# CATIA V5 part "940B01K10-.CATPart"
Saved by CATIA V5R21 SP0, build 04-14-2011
Part number: 940B01K10-
Bounding box of the stored display mesh (mm): x -77.949 to 49.351, y -15.698 to 19.302, z -6.85 to 7.15
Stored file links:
  C:\Users\ALI OZGUN\Desktop\alhan\940B01K10-.CATPart
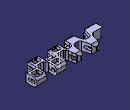
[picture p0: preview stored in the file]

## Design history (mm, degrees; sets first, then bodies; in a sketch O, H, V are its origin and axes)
Set1 "CURVE"
  DatumCurve1 to DatumCurve105
Set2 "SURFACE"
  Plane1: type 1Curve, Element1 DatumCurve19
  Sketch1 on Plane1, origin (0, 0, -3.1959), H (1, 0, 0), V (0, -1, 0)
    line L1 (49.4472, 15.9983) -> (32.7694, 15.9983)
    line L2 (48.5473, -19.0017) -> (65.7661, -19.0017)
    line L3 (-61.2339, -0.5841) -> (-61.2339, 15.0809)
    line L4 (65.7661, -19.0017) -> (65.7661, 3.0782)
    point P1 (65.7661, -19.0017)
    line L5 (49.4472, 15.9983) -> (49.0081, 3.1001)
    line L6 (49.0081, 3.1001) -> (53.2715, -2.5577)
    line L7 (53.2715, -2.5577) -> (61.843, -2.5577)
    point P2 (49.0081, 3.1001)
    point P3 (53.2715, -2.5577)
    point P4 (49.4472, 15.9983)
    line L8 (61.843, -2.5577) -> (65.7661, 3.0782)
    point P5 (61.843, -2.5577)
    point P6 (65.7661, 3.0782)
    reference intersected line E1 through (0, 0) direction (0, 1) from yz-plane
    reference intersected line E2 through (0, 0) direction (0, 1) from yz-plane
    construction line L9 (41.1083, 0) -> (41.1083, 12.9106)
    construction line L10 (41.1083, 12.9106) -> (46.3559, 12.9106)
    construction line L11 (46.3559, 12.9106) -> (46.3559, 3.0133)
    construction line L12 (46.3559, 3.0133) -> (41.1083, 3.0133)
    point P7 (46.3559, 12.9106)
    point P8 (46.3559, 3.0133)
    point P9 (41.1083, 12.9106)
    point P10 (41.1083, 3.0133)
    line L13 (41.1083, 0) -> (50.5276, 0)
    line L14 (48.5473, -19.0017) -> (50.5276, 0)
    point P11 (50.5276, 0)
    point P12 (41.1083, 0)
    point P13 (48.5473, -19.0017)
    point P14 (35.8607, 12.9106)
    point P15 (41.1083, 12.9106)
    construction line L15 (41.1083, 12.9106) -> (35.8607, 12.9106)
    point P16 (35.8607, 3.0133)
    construction line L16 (35.8607, 12.9106) -> (35.8607, 3.0133)
    point P17 (41.1083, 3.0133)
    construction line L17 (35.8607, 3.0133) -> (41.1083, 3.0133)
    point P18 (31.6891, 0)
    point P19 (41.1083, 0)
    line L18 (41.1083, 0) -> (31.6891, 0)
    point P20 (33.6694, -19.0017)
    line L19 (33.6694, -19.0017) -> (31.6891, 0)
    point P21 (16.4506, -19.0017)
    line L20 (33.6694, -19.0017) -> (16.4506, -19.0017)
    point P22 (16.4506, 3.0782)
    line L21 (16.4506, -19.0017) -> (16.4506, 0)
    point P23 (20.3736, -2.5577)
    line L22 (20.3736, -2.5577) -> (16.5464, 2.9405)
    point P24 (28.9451, -2.5577)
    line L23 (28.9451, -2.5577) -> (20.3736, -2.5577)
    point P25 (33.2086, 3.1001)
    line L24 (33.2086, 3.1001) -> (28.9451, -2.5577)
    point P26 (32.7694, 15.9983)
    line L25 (32.7694, 15.9983) -> (33.2086, 3.1001)
    axis line L26 (24.8802, -15.8106) -> (24.8802, 20.8842)
    line L27 (16.991, 15.9983) -> (16.5464, 2.9405)
    point P29 (13.8998, 3.0133)
    point P30 (13.8998, 12.9106)
    construction line L28 (13.8998, 12.9106) -> (13.8998, 3.0133)
    point P31 (8.6521, 0)
    line L29 (8.6521, 0) -> (16.4506, 0)
    point P32 (8.6521, 0)
    line L30 (8.6521, 0) -> (-0.2618, 0)
    point P33 (3.4045, 3.0133)
    point P34 (3.4045, 12.9106)
    construction line L31 (3.4045, 12.9106) -> (3.4045, 3.0133)
    point P35 (8.6521, 3.0133)
    construction line L32 (3.4045, 3.0133) -> (8.6521, 3.0133)
    point P36 (8.6521, 3.0133)
    construction line L33 (13.8998, 3.0133) -> (8.6521, 3.0133)
    point P37 (8.6521, 12.9106)
    construction line L34 (8.6521, 12.9106) -> (3.4045, 12.9106)
    point P38 (8.6521, 12.9106)
    construction line L35 (8.6521, 12.9106) -> (13.8998, 12.9106)
    point P39 (0.3133, 15.9983)
    line L36 (0.3133, 15.9983) -> (0.7524, 3.1001)
    line L37 (0.7524, 3.1001) -> (-3.8134, -2.9589)
    line L38 (16.991, 15.9983) -> (0.3133, 15.9983)
    line L39 (-0.2618, 0) -> (0.5916, -19.0017)
    line L40 (-12.1477, -5.1469) -> (-12.4932, -19.0017)
    line L41 (-3.8134, -2.9589) -> (-12.4906, -2.9589)
    line L42 (-12.4906, -2.9589) -> (-12.6654, 12.1222)
    line L43 (-29.6656, -3.0126) -> (-25.0164, 15.9983)
    line L44 (-39.0662, -3.1542) -> (-29.6656, -3.0126)
    line L45 (-44.327, 15.3928) -> (-39.0662, -3.1542)
    line L46 (-43.9186, 0.391) -> (-38.7475, -19.0017)
    line L47 (-43.9186, 0.391) -> (-61.2339, -0.5841)
    line L48 (-61.2339, 15.0809) -> (-44.327, 15.3928)
    line L49 (-16.4275, 15.9983) -> (-25.0164, 15.9983)
    line L50 (-16.4275, 15.9983) -> (-12.6654, 12.1222)
    line L51 (-24.9197, 0.2086) -> (-29.3974, -19.0017)
    line L52 (-24.9197, 0.2086) -> (-16.3942, 0.2086)
    line L53 (-16.3942, 0.2086) -> (-12.1477, -5.1469)
    line L54 (-29.3974, -19.0017) -> (-38.7475, -19.0017)
    line L55 (0.5916, -19.0017) -> (-12.4932, -19.0017)
    distance L2 L1 = 35
    distance L3 L4 = 127
    angle E1 L5 = 1.95
    angle E2 L6 = 37
    horizontal: L1 H, L2 H, L7 H, L10 H, L12 H, L13 H, L38 H, L41 H, L49 H, L52 H
    fix: L1, L9
    vertical: L3 V, L4 V, L9 V, L11 V, L26 V
    coincidence: P10 L9, L1 L38, P22 L22, P22 L21, L38 L49, L20 L54, L20 L55
    symmetry: P7 P14 L9, P9 P15 L9, L10 L15 L9, P8 P16 L9, L11 L16 L9, P10 P17 L9, L12 L17 L9, P11 P18 L9, P12 P19 L9, L13 L18 L9, P13 P20 L9, L14 L19 L9, P1 P21 L9, L2 L20 L9, P6 P22 L9, L4 L21 L9, P5 P23 L9, L8 L22 L9, P3 P24 L9, L7 L23 L9, P2 P25 L9, L6 L24 L9, P4 P26 L9, L5 L25 L9, L25 L27 L26, P16 P29 L26, P14 P30 L26, L16 L28 L26, P19 P31 L26, L18 L29 L26, P12 P32 L26, L13 L30 L26, P8 P33 L26, P7 P34 L26, L11 L31 L26, P10 P35 L26, L12 L32 L26, P17 P36 L26, L17 L33 L26, P9 P37 L26, L10 L34 L26, P15 P38 L26, L15 L35 L26, P4 P39 L26, L5 L36 L26, L6 L37 L26
  Sweep1: type Segment, GuideCrv Sketch1, Length1 4, Length2 5, Angle -1, DraftDirection (0, 0, 1)
  Sketch2 on yz-plane, origin (0, 0, 0), H (0, 1, 0), V (0, 0, 1)
    line L1 (-24.9191, -6.9968) -> (50.389, -6.9968)
    horizontal: L1 H
  Extrude1: Element1 Sketch2, Lim1 80, Lim2 80
  Trim1: Trimmed (Sweep1; Extrude1)
  Sketch3 on yz-plane, origin (0, 0, 0), H (0, 1, 0), V (0, 0, 1)
    line L1 (-48.3055, 0) -> (52.6647, 0)
    horizontal: L1 H
    coincidence: O L1
  Extrude2: Element1 Sketch3, Lim1 80, Lim2 80
  Trim2: Trimmed (Trim1; Extrude2)
  Extrude3: Element1 Sketch7, Lim1 10, Lim2 10
  Translate1: ToTransfor Extrude3, Direction (1, 0, 0), Length 32.6
  Extrude4: Element1 Sketch8, Lim1 10, Lim2 10
  Translate2: ToTransfor Extrude4, Direction (1, 0, 0), Length 32.8
  Sweep2: type Segment, GuideCrv Sketch11, Length1 10, Length2 5, Angle -1, DraftDirection (0, 0, 1)
  Translate3: ToTransfor Sweep2, Direction (1, 0, 0), Length -32.8
  Sketch4 on face of CloseSurface1, origin (0, 0, 0), H (1, 0, 0), V (0, 1, 0)
    line L1 (-3.8486, 19.8441) -> (1.0015, 13.5162)
  Sweep3: type Segment, GuideCrv Sketch4, Length1 10, Length2 5, Angle 1, DraftDirection (0, 0, 1)
  Plane2: type 1Curve, Element1 DatumCurve99
  Sketch5 on Plane2, origin (0, 0, -5.2979), H (1, 0, 0), V (0, -1, 0)
    line L1 (-37.6706, -7.3878) -> (-35.3775, -14.835)
    line L2 (-32.6098, -14.835) -> (-30.9175, -7.3878)
    offset line E2 (-36.4878, -14.835) -> (-31.7318, -14.835) from edge [face of Mirror1 | face of CloseSurface1]
    offset line E3 (-35.3775, -14.835) -> (-32.6098, -14.835) from edge [face of Mirror1 | face of CloseSurface1]
    line L3 (-37.6706, -7.3878) -> (-30.9175, -7.3878)
    point P5 (-36.4878, -7.3878)
    point P6 (-31.7318, -7.3878)
    construction line L4 (-36.4878, -14.835) -> (-36.4878, -7.3878)
    construction line L5 (-31.7318, -14.835) -> (-31.7318, -7.3878)
    distance E2 L3 = 7.4472
    perpendicularity: L4 E2, L4 L3, L5 E2, L5 L3
    coincidence: P5 L3, P6 L3
  Sweep4: type Segment, GuideCrv Sketch5, Length1 5, Length2 5, Angle -1, DraftDirection (0, 0, 1)
  Sketch6 on yz-plane, origin (0, 0, 0), H (0, 1, 0), V (0, 0, 1)
    line L1 (-47.946, -0.4507) -> (26.6531, -0.4507)
    horizontal: L1 H
  Extrude5: Element1 Sketch6, Lim1 100, Lim2 100
  Trim3: Trimmed (Sweep4; Extrude5)
  Sweep5: type Segment, GuideCrv Sketch12, Length1 5, Length2 5, Angle -1, DraftDirection (0, 0, 1)
  Trim4: Trimmed (Extrude5; Sweep5)
  MultiExtract1: ListOfMultiExtractConstraints (MultiExtractConstraint face of Split9; MultiExtractConstraint face of Fillet45; MultiExtractConstraint face of Split9; MultiExtractConstraint face of Fillet47; MultiExtractConstraint face of Split9; MultiExtractConstraint face of Split9; MultiExtractConstraint face of Fillet49; MultiExtractConstraint face of Fillet48; MultiExtractConstraint face of Fillet46; MultiExtractConstraint face of Split9)
  Extrapol1: ToExtrapol edge of MultiExtract1, Support MultiExtract1, Length 10
  Extrapol2: ToExtrapol edge [end face of Pocket4 | face of Pocket5 from Sketch15.E2], Support face of Pocket5 from Sketch15.E2, Length 10
  Trim5: Trimmed (Extrapol1; Extrapol2)
  Extrapol3: ToExtrapol edge of MultiExtract1, Support Trim5, Length 1
  Extrapol4: ToExtrapol edge [face of Pocket4 from Sketch14.L2 | face of CloseSurface1], Support face of Pocket4 from Sketch14.L2, Length 5
  Extrapol5: ToExtrapol edge [face of Pocket4 from Sketch14.L1 | face of Mirror1], Support face of Pocket4 from Sketch14.L1, Length 5
  Extrapol6: ToExtrapol edge [face of Mirror1 | face of Pocket4 from Sketch14.L4], Support face of Pocket4 from Sketch14.L4, Length 5
  Trim6: Trimmed (Extrapol6; Extrapol5; Extrapol4)
  Extrapol7: ToExtrapol edge [face of CloseSurface1 | face of Split10], Support face of Split10, Length 5
  Trim7: Trimmed (Extrapol7; Trim6)
  Extrapol8: ToExtrapol edge [face of CloseSurface1 | face of Pocket4 from Sketch14.L3], Support face of Pocket4 from Sketch14.L3, Length 5
  Trim8: Trimmed (Extrapol8; Trim7)
Set3
  CLDGeom1 "4_1.1"
  Plane3: type Offset, RefPlane yz-plane, Offset -63
Body1 (main body)
  CloseSurface1: CloseElement Trim2
  Sketch7 on face of CloseSurface1, origin (0, 0, -6.9968), H (1, 0, 0), V (0, -1, 0)
    line L1 (3.5232, 12.867) -> (13.7904, 12.867)
    line L2 (13.7904, 12.867) -> (13.7904, 3.1238)
    line L3 (13.7904, 3.1238) -> (3.5232, 3.1238)
    line L4 (3.5232, 3.1238) -> (3.5232, 12.867)
    horizontal: L1 H, L3 H
    vertical: L2 V, L4 V
    fix: L4, L1
  Split1: SplitPlane Extrude3
  Split2: SplitPlane Translate1
  Sketch8 on face of CloseSurface1, origin (0, 0, -6.9968), H (1, 0, 0), V (0, -1, 0)
    line L1 (19.6709, -6.2611) -> (30.062, -6.2611)
    line L2 (30.062, -6.2611) -> (30.062, -15.6449)
    line L3 (30.062, -15.6449) -> (19.6709, -15.6449)
    line L4 (19.6709, -15.6449) -> (19.6709, -6.2611)
    horizontal: L1 H, L3 H
    vertical: L2 V, L4 V
    fix: L1, L4, L2
  Split3: SplitPlane Translate2
  Split4: SplitPlane Extrude4
  Sketch9 on face of CloseSurface1, origin (0, 0, -6.9968), H (1, 0, 0), V (0, -1, 0)
    line L1 (-8.0734, -6.1533) -> (-4.0044, -6.1533)
    line L2 (-4.0044, -6.1533) -> (-4.0044, -14.5157)
    line L3 (-4.0044, -14.5157) -> (-8.0734, -14.5157)
    line L4 (-8.0734, -14.5157) -> (-8.0734, -6.1533)
    horizontal: L1 H, L3 H
    vertical: L2 V, L4 V
  Pocket1: profile Sketch9, direction (0, 0, 1), length 20
  Sketch10 on face of CloseSurface1, origin (0, 0, -6.9968), H (1, 0, 0), V (0, -1, 0)
    line L1 (-16.7652, 4.7837) -> (-23.421, 4.7837)
    line L2 (-21.5701, 11.8402) -> (-16.7652, 11.8402)
    line L3 (-16.7652, 11.8402) -> (-16.7652, 4.7837)
    line L4 (-23.421, 4.7837) -> (-21.5701, 11.8402)
    horizontal: L1 H, L2 H
    vertical: L3 V
  Pocket2: profile Sketch10, direction (0, 0, 1), length 20
  Draft1: Angle 1, Neutral face of CloseSurface1, PullDir face of CloseSurface1, SupportToDraft (face of Split3; face of Split3; face of Split3; face of Split3; face of Split2; face of Split2; face of Split2; face of Split2; face of Split4; face of Split4; face of Split4; face of Split4; face of Split1; face of Split1; face of Split1; face of Split1; face of Pocket1 from Sketch9.L2; face of Pocket1 from Sketch9.L4; face of Pocket1 from Sketch9.L3; face of Pocket1 from Sketch9.L1; face of Pocket2 from Sketch10.L1; face of Pocket2 from Sketch10.L3; face of Pocket2 from Sketch10.L2; face of Pocket2 from Sketch10.L4)
  Chamfer1: length 2.85, angle 44, on edge [face of CloseSurface1 | face of CloseSurface1] (x8)
  Thickness1: Face (face of Chamfer1; face of Chamfer1; face of Chamfer1; face of Chamfer1), Thickness 0.15
  Thickness2: Face (face of Chamfer1; face of Chamfer1; face of Chamfer1; face of Chamfer1), Thickness 0.4
  Sketch11 on face of CloseSurface1, origin (0, 0, 0), H (1, 0, 0), V (0, 1, 0)
    line L1 (57.6565, 24.4948) -> (67.109, 12.822)
    line L2 (46.3763, 10.5649) -> (57.6565, 24.4948)
    angle V L2 = 39
    angle L1 V = 39
  Split5: SplitPlane Sweep2
  Split6: SplitPlane Translate3
  Split7: SplitPlane Sweep3
  Thickness3: Face face of Split7, Thickness -0.1
  Fillet1: radius 0.75, on edge [face of CloseSurface1 | face of CloseSurface1]
  Fillet2: radius 4, on edge [face of Split6 | face of CloseSurface1]; edge [face of Split5 | face of CloseSurface1]
  Fillet3: radius 4.5, on edge [face of Split6 | face of CloseSurface1]; edge [face of Split5 | face of CloseSurface1]
  Fillet4: radius 4.5, on edge [face of Split6 | face of CloseSurface1]; edge [face of Split5 | face of CloseSurface1]
  Fillet5: radius 4.5, on edge [face of CloseSurface1 | face of Split5]; edge [face of CloseSurface1 | face of Split6]
  Fillet6: radius 3.5, on edge [face of CloseSurface1 | face of CloseSurface1] (x4)
  Fillet7: radius 3, on edge [face of Split7 | face of CloseSurface1]
  Fillet8: radius 3, on edge [face of Split7 | face of CloseSurface1]
  Fillet9: radius 4, on edge [face of CloseSurface1 | face of CloseSurface1]
  Fillet10: radius 3, on edge [face of CloseSurface1 | face of CloseSurface1]
  Fillet11: radius 3, on edge [face of CloseSurface1 | face of CloseSurface1]
  Fillet12: radius 3, on edge [face of CloseSurface1 | face of CloseSurface1]
  Fillet13: radius 3, on edge [face of CloseSurface1 | face of CloseSurface1]
  Fillet14: radius 3, on edge [face of CloseSurface1 | face of CloseSurface1]
  Fillet15: radius 3, on edge [face of CloseSurface1 | face of CloseSurface1]
  Fillet16: radius 3, on edge [face of CloseSurface1 | face of CloseSurface1]
  Fillet17: radius 3, on edge [face of CloseSurface1 | face of CloseSurface1] (x2)
  Fillet18: radius 0.75, on edge [face of CloseSurface1 | face of CloseSurface1]
  Fillet19: radius 0.75, on edge [face of CloseSurface1 | face of CloseSurface1]
  Fillet20: radius 3, on edge [face of CloseSurface1 | face of CloseSurface1] (x4)
  Fillet21: radius 0.75, on edge [face of CloseSurface1 | face of CloseSurface1] (x2)
  Fillet22: radius 3, on edge [face of CloseSurface1 | face of CloseSurface1] (x2)
  Fillet23: radius 4, on edge [face of CloseSurface1 | face of CloseSurface1]
  Fillet24: radius 3, on edge [face of CloseSurface1 | face of CloseSurface1]
  Fillet25: radius 1.5, on edge [face of CloseSurface1 | face of CloseSurface1] (x2)
  Fillet26: radius 3, on edge [face of CloseSurface1 | face of CloseSurface1] (x2)
  Fillet27: radius 3, on edge [face of CloseSurface1 | face of CloseSurface1]
  Fillet28: radius 0.5, on edge [face of CloseSurface1 | face of CloseSurface1]
  Fillet29: radius 0.5, on edge [face of CloseSurface1 | face of CloseSurface1]
  Fillet30: radius 2.75, on edge [face of Split4 | face of Split4] (x2); edge [face of Split3 | face of Split3] (x2)
  Fillet31: radius 2, on edge [face of Split4 | face of Split4] (x2); edge [face of Split3 | face of Split3] (x2)
  Fillet32: radius 2.75, on edge [face of Split2 | face of Split2] (x2)
  Fillet33: radius 2, on edge [face of Split2 | face of Split2] (x2)
  Fillet34: radius 1.5, on edge [face of Split1 | face of Split1] (x2)
  Fillet35: radius 1.75, on edge [face of Split1 | face of Split1] (x2)
  TritangentFillet1: Face1 face of Pocket1 from Sketch9.L4, Face2 face of Pocket1 from Sketch9.L2, RemoveFace face of Pocket1 from Sketch9.L1
  TritangentFillet2: Face1 face of Pocket1 from Sketch9.L4, Face2 face of Pocket1 from Sketch9.L2, RemoveFace face of Pocket1 from Sketch9.L3
  Fillet36: radius 1.75, on edge [face of Pocket2 from Sketch10.L2 | face of Pocket2 from Sketch10.L3]
  Fillet37: radius 1, on edge [face of Pocket2 from Sketch10.L4 | face of Pocket2 from Sketch10.L2]
  Fillet38: radius 1.5, on edge [face of Pocket2 from Sketch10.L4 | face of Pocket2 from Sketch10.L1]
  Fillet39: radius 1.75, on edge [face of Pocket2 from Sketch10.L3 | face of Pocket2 from Sketch10.L1]
  Fillet40: radius 0.5, on edge [face of CloseSurface1 | face of CloseSurface1] (x8)
  Fillet41: radius 0.5, on edge [face of Chamfer1 | face of CloseSurface1]
  Fillet42: radius 0.5, on edge [face of Chamfer1 | face of CloseSurface1]
  Fillet43: radius 0.5, on edge [face of Chamfer1 | face of CloseSurface1] (x2)
  Fillet44: radius 0.5, on edge [face of Chamfer1 | face of CloseSurface1] (x4)
  Thickness4: Face face of CloseSurface1, Thickness 0.15
  Mirror1: of the body so far, about face of CloseSurface1
  Split8: SplitPlane Trim3
  Sketch12 on Plane2, origin (0, 0, -5.2979), H (1, 0, 0), V (0, -1, 0)
    line L1 (-57.1409, 11.1692) -> (-47.5031, 11.1692)
    line L2 (-46.3543, 7.2877) -> (-46.3543, 4.9902)
    line L3 (-46.3543, 4.9902) -> (-57.1409, 4.9902)
    line L4 (-57.1409, 4.9902) -> (-57.1409, 11.1692)
    line L5 (-47.5031, 11.1692) -> (-46.3543, 7.2877)
    horizontal: L1 H, L3 H
    vertical: L2 V, L4 V
  Split9: SplitPlane Trim4
  Fillet45: radius 2, on edge [face of Split9 | face of Split9]
  Fillet46: radius 2, on edge [face of Split9 | face of Split9]
  Fillet47: radius 1.9, on edge [face of Split9 | face of Split9]
  Fillet48: radius 2, on edge [face of Split9 | face of Split9]
  Fillet49: radius 2, on edge [face of Split9 | face of Split9]
  Fillet50: radius 2, on edge [face of Split8 | face of Split8]
  Fillet51: radius 2, on edge [face of Split8 | face of Split8]
  Fillet52: radius 1.5, on edge [face of Split8 | face of Split8] (x2)
  Sketch13 on yz-plane, origin (0, 0, 0), H (0, 1, 0), V (0, 0, 1)
    line L1 (4.7142, -2.0988) -> (16.0181, -2.0988)
    line L2 (16.0181, -2.0988) -> (16.0181, 2.7411)
    line L3 (16.0181, 2.7411) -> (4.7142, 2.7411)
    line L4 (4.7142, 2.7411) -> (4.7142, -2.0988)
    horizontal: L1 H, L3 H
    vertical: L2 V, L4 V
  Pocket3: profile Sketch13, direction (-1, 0, 0), length 111, opposite side length 100
  Sketch14 on yz-plane, origin (0, 0, 0), H (0, 1, 0), V (0, 0, 1)
    line L1 (-13.6557, 2.8812) -> (-2.4057, 2.8812)
    line L2 (-2.4057, 2.8812) -> (-2.4057, -2.1188)
    line L3 (-2.4057, -2.1188) -> (-13.6557, -2.1188)
    line L4 (-13.6557, -2.1188) -> (-13.6557, 2.8812)
    distance L1 L3 = 5
    distance L4 L2 = 11.25
    horizontal: L1 H, L3 H
    vertical: L2 V, L4 V
    fix: L1
  Pocket4: profile Sketch14, direction (-1, 0, 0), length 55, opposite side length 100
  Sketch15 on Plane3, origin (-63, 0, 0), H (0, 1, 0), V (0, 0, 1)
    projected line E1 (16.0181, 2.7411) -> (4.7142, 2.7411) from edge [face of Pocket3 from Sketch13.L3 | face of Mirror1]
    projected line E2 (2.9895, 2.7411) -> (-6.2509, 2.7411) from edge [face of Pocket3 from Sketch13.L3 | face of Mirror1]
    projected line E3 (16.0181, -2.0988) -> (4.7142, -2.0988) from edge [face of CloseSurface1 | face of Pocket3 from Sketch13.L1]
    projected line E4 (2.9895, -2.0988) -> (-6.2509, -2.0988) from edge [face of CloseSurface1 | face of Pocket3 from Sketch13.L1]
    line L1 (-6.2509, -2.0988) -> (-6.2509, 2.7411)
    line L2 (2.9895, 2.7411) -> (2.9895, -2.0988)
    vertical: L1 V, L2 V
  Pocket5: profile Sketch15, direction (1, 0, 0), length 11
  Split10: SplitPlane Extrapol3
  Split11: SplitPlane Trim8
  Align1: SewingRemoveFace face of Split11, SplitPlane face of Split10
  Thickness5: Face (face of Split11; face of Pocket5 from Sketch15.E4), Thickness 0.15
  Align2: SewingRemoveFace face of Pocket5 from Sketch15.E4, SplitPlane face of Split11
  RemoveFace1: RemoveFaces (face of Pocket4 from Sketch14.L3; face of Pocket4 from Sketch14.L1; face of Pocket4 from Sketch14.L4; face of Pocket4 from Sketch14.L2; face of Pocket4 from Sketch14.L2; face of Pocket4 from Sketch14.L1; face of Pocket4 from Sketch14.L3; face of Pocket4 from Sketch14.L4; face of Pocket4 from Sketch14.L4; face of Pocket4 from Sketch14.L1; face of Pocket4 from Sketch14.L2; face of Pocket4 from Sketch14.L3)
  RemoveFace2: RemoveFaces (face of Pocket3 from Sketch13.L3; face of Pocket3 from Sketch13.L4; face of Pocket3 from Sketch13.L1; face of Pocket3 from Sketch13.L2; face of Pocket3 from Sketch13.L4; face of Pocket3 from Sketch13.L3; face of Pocket3 from Sketch13.L1; face of Pocket3 from Sketch13.L2; face of Pocket3 from Sketch13.L3; face of Pocket3 from Sketch13.L4; face of Pocket3 from Sketch13.L2; face of Pocket3 from Sketch13.L1)
  Draft2: Angle 0, Neutral xy-plane, PullDir xy-plane, SupportToDraft (face of Mirror1; face of Split1; face of Mirror1; face of Split2; face of Mirror1; face of Fillet31; face of Mirror1; face of Fillet31; face of Mirror1; face of Fillet36)
  RemoveFace3: RemoveFaces (face of Split10; face of Split11; face of Split10; face of Split10; face of Split10; face of Split10; face of Split10; face of Split10; face of Split10; face of Split10; face of Split10; end face of Pocket5; face of Split11; face of Split11; face of Pocket5 from Sketch15.L1; face of Split11)
  Sketch16 on face of CloseSurface1, origin (0, 0, -6.9968), H (1, 0, 0), V (0, -1, 0)
    projected curve E1 from edge [face of Split11 | face of Split10]
    projected line E2 (-55.083, 5.0483) -> (-48.3121, 5.0483) from edge [face of Split10 | face of Split11]
    projected curve E3 from edge [face of Split11 | face of Split10]
    projected line E4 (-46.4946, 7.5571) -> (-47.1226, 9.6789) from edge [face of Split10 | face of Split11]
    projected arc E5 centre (-48.414, 6.9893) radius 2.0016 from (-46.4124, 6.9896) to (-46.4946, 7.5571) ccw from edge [face of Split11 | face of Split10]
    projected curve E6 from edge [face of Split11 | face of Split10]
    projected line E7 (-49.0401, 11.1111) -> (-55.083, 11.1111) from edge [face of Split10 | face of Split11]
    projected curve E8 from edge [face of Split11 | face of Split10]
    line L1 (-57.0827, 9.1114) -> (-57.0827, 7.048)
    projected line E9 (-46.4124, 6.948) -> (-46.4124, 6.9896) from edge [face of Split10 | face of Split11]
    projected line E10 (-33.4926, -7.4437) -> (-34.8869, -7.4437) from edge [face of Split8 | face of Pocket3 from Sketch13.L1]
    projected curve E11 from edge [face of Pocket3 from Sketch13.L1 | face of Fillet51]
    projected line E12 (-32.3891, -13.6117) -> (-31.5426, -9.8864) from edge [face of Split8 | face of Pocket3 from Sketch13.L1]
    projected curve E13 from edge [face of Pocket3 from Sketch13.L1 | face of Fillet52]
    projected curve E14 from edge [face of Fillet52 | face of Pocket3 from Sketch13.L1]
    projected line E15 (-34.2288, -14.7792) -> (-33.8515, -14.7792) from edge [face of Split8 | face of Pocket3 from Sketch13.L1]
    projected line E16 (-36.798, -10.0318) -> (-35.6622, -13.7207) from edge [face of Split8 | face of Pocket3 from Sketch13.L1]
    projected curve E17 from edge [face of Fillet50 | face of Pocket3 from Sketch13.L1]
    vertical: L1 V
  Draft3: Angle 0, Neutral face of Pocket3 from Sketch13.L1, PullDir face of Pocket3 from Sketch13.L1, SupportToDraft face of Fillet52
  RemoveFace4: RemoveFaces (face of Pocket3 from Sketch13.L1; face of Pocket3 from Sketch13.L4; face of Pocket3 from Sketch13.L3; face of Pocket3 from Sketch13.L2; face of Split8; face of Fillet52; face of Split8; face of Fillet52; face of Split8; face of Fillet50; face of Split8; face of Fillet51)
  Pocket6: profile Sketch16, direction (0, 0, 1), up to xy-plane
  Sketch17 on yz-plane, origin (0, 0, 0), H (0, 1, 0), V (0, 0, 1)
    construction line L1 (-11.1983, 0.15) -> (-5.1983, 0.15)
    point P1 (-11.1983, 0.15)
    line L2 (-11.1983, 2.65) -> (-5.1983, 2.65)
    line L3 (-5.1983, -2.35) -> (-11.1983, -2.35)
    arc A1 centre (-5.1983, 0.15) radius 2.5 from (-5.1983, 2.65) to (-5.1983, -2.35) cw
    arc A2 centre (-11.1983, 0.15) radius 2.5 from (-11.1983, -2.35) to (-11.1983, 2.65) cw
    point P3 (-11.1983, 2.65)
    point P4 (-5.1983, 2.65)
    point P5 (-5.1983, -2.35)
    point P6 (-11.1983, -2.35)
    reference projected line E1 (12.9961, 0.15) -> (-0.8745, 0.15) from edge [face of Mirror1 | face of CloseSurface1]
    construction line L4 (19.0601, 0.15) -> (-16.0567, 0.15)
    axis line L5 (1.5017, 0.15) -> (1.5017, 16.5006)
    point P7 (1.5017, 0.15)
    construction line L6 (14.2017, 0.15) -> (8.2017, 0.15)
    point P11 (14.2017, 2.65)
    point P12 (8.2017, 2.65)
    point P13 (8.2017, -2.35)
    point P14 (14.2017, -2.35)
    line L7 (14.2017, 2.65) -> (8.2017, 2.65)
    line L8 (8.2017, -2.35) -> (14.2017, -2.35)
    arc A3 centre (8.2017, 0.15) radius 2.5 from (8.2017, 2.65) to (8.2017, -2.35) ccw
    arc A4 centre (14.2017, 0.15) radius 2.5 from (14.2017, -2.35) to (14.2017, 2.65) ccw
    distance L1 L2 = 2.5
    distance P1 L5 = 12.7
    length L1 = 6
    horizontal: L1 H, L4 H
    tangency: A1 L2, A2 L2, A1 L3, A2 L3
    coincidence: L1 E1
    midpoint: P7 L4
    vertical: L5 V
    symmetry: L1 L6 L5, P3 P11 L5, P4 P12 L5, P5 P13 L5, P6 P14 L5, L2 L7 L5, L3 L8 L5, A1 A3 L5, A2 A4 L5
  Sketch18 on xy-plane, origin (0, 0, 0), H (1, 0, 0), V (0, 1, 0)
    line L1 (-59.6762, 27.1723) -> (64.7084, 27.1723)
    line L2 (64.7084, 27.1723) -> (64.7084, -29.9789)
    line L3 (64.7084, -29.9789) -> (-59.6762, -29.9789)
    line L4 (-59.6762, -29.9789) -> (-59.6762, 27.1723)
    reference projected line E1 through (65.2084, 0) direction (0, -1) from axis of face of Mirror1
    reference projected line E2 (-60.6762, -12.5832) -> (-60.6762, -0.0059) from edge [face of Mirror1 | face of Mirror1]
    distance L2 E1 = 0.5
    distance L4 E2 = 1
    horizontal: L1 H, L3 H
    vertical: L2 V, L4 V
  Pocket7: profile Sketch18, direction (0, 0, -1), length 94, mirrored extent, outer side
  Thickness6: Face face of Pocket7 from Sketch18.L4, Thickness 2
  Thickness7: Face face of Pocket7 from Sketch18.L4, Thickness 1.115
  Pocket8: profile Sketch17, direction (-1, 0, 0), length 94, mirrored extent
  Sketch19 on yz-plane, origin (0, 0, 0), H (0, 1, 0), V (0, 0, 1)
    arc A1 centre (-5.1983, 0.15) radius 2.5 from (-5.1983, 2.65) to (-5.1983, -2.35) ccw
    point P10 (-5.1983, -2.35)
    line L1 (-11.1983, 2.65) -> (-5.1983, 2.65)
    arc A2 centre (-11.1982, 0.15) radius 2.5 from (-11.1983, 2.65) to (-13.6983, 0.15) ccw
    arc A3 centre (-11.1982, 0.15) radius 2.5 from (-13.6983, 0.15) to (-11.1983, -2.35) ccw
    line L2 (-5.1983, -2.35) -> (-11.1983, -2.35)
    construction arc A4 centre (-5.1983, 0.15) radius 2.5 from (-2.6983, 0.15) to (-5.1983, 2.65) ccw
    coincidence: A1 A4, L2 P10
  Pad1: profile Sketch19, direction (-1, 0, 0), length 94, opposite side up to face of Pocket6 from Sketch16.L1
  Split12: SplitPlane face of Pocket7 from Sketch18.L4
Body2
  Solid1: linked copy from another document
  Translate4: ToTransfor Solid1, Direction zx-plane, Length -19
Body3
  Solid2: solid without history
  Translate5: Direction edge [face of Solid3 | face of Solid3], ToTransfor Solid2, Length 15
Body4
  Solid3: solid without history
  Split13: SplitPlane face of Solid3
  Body5
    Sketch20 on face of Solid3, origin (0, 0, -6.85), H (1, 0, 0), V (0, -1, 0)
      line L1 (-77.9488, 12.497) -> (-77.9488, 2.8937)
      line L2 (-75.055, 0) -> (-62.8479, 0)
      line L3 (-58.0492, -3.5955) -> (-54.3874, -16.1072)
      line L4 (-50.1239, -19.3017) -> (-48.9356, -19.3017)
      line L5 (-43.8676, -15.3198) -> (-40.7729, -2.6121)
      point P1 (-40.1368, 0)
      line L6 (-37.4484, 0) -> (-33.9228, 0)
      line L7 (-28.7341, -2.6853) -> (-28.7254, -2.6976)
      line L8 (-26.6939, -9.0873) -> (-26.6939, -16.7891)
      point P2 (-26.6939, -19.3017)
      line L9 (-24.1812, -19.3017) -> (-23.1488, -19.3017)
      line L10 (-19.4647, -17.5249) -> (-18.7392, -16.613)
      line L11 (-16.7488, -10.9137) -> (-16.7488, -5.4517)
      line L12 (-18.0368, -2.7398) -> (-21.509, -2.7398)
      line L13 (-27.885, 3.6363) -> (-27.885, 12.2509)
      line L14 (-27.885, 12.2509) -> (-31.292, 15.6983)
      line L15 (-31.292, 15.6983) -> (-40.4229, 15.6983)
      line L16 (-40.4229, 15.6983) -> (-44.4156, -0.6971)
      line L17 (-47.975, -3.4937) -> (-52.1939, -3.4937)
      line L18 (-55.7282, -0.8455) -> (-59.3074, 11.3836)
      line L19 (-65.0658, 15.6983) -> (-74.7475, 15.6983)
      projected line E1 (-16.6488, -5.3517) -> (-13.9346, -2.6375) from edge [face of Solid3 | face of Solid3]
      projected line E2 (-16.7488, -5.4517) -> (-13.9346, -2.6375) from edge [face of Solid3 | face of Solid3]
      projected line E3 (-18.1594, -2.8624) -> (-16.5488, -1.2517) from edge [face of Solid3 | face of Solid3]
      projected line E4 (-18.0368, -2.7398) -> (-16.5488, -1.2517) from edge [face of Solid3 | face of Solid3]
      line L20 (-13.9346, -2.6375) -> (-16.5488, -1.2517)
      arc A1 centre (-21.509, 3.6363) radius 6.376 from (-21.509, -2.7398) to (-27.885, 3.6363) cw
      arc A2 centre (-37.7581, -9.0873) radius 11.0643 from (-28.7254, -2.6976) to (-26.6939, -9.0873) cw
      arc A3 centre (-33.9228, -6.3557) radius 6.3557 from (-33.9228, 0) to (-28.7341, -2.6853) cw
      arc A4 centre (-37.4484, -3.4217) radius 3.4217 from (-37.4484, 0) to (-40.7729, -2.6121) ccw
      arc A5 centre (-25.9033, -10.9137) radius 9.1545 from (-16.7488, -10.9137) to (-18.7392, -16.613) cw
      arc A6 centre (-23.1488, -14.5941) radius 4.7077 from (-23.1488, -19.3017) to (-19.4647, -17.5249) ccw
      arc A7 centre (-24.1812, -16.7891) radius 2.5127 from (-26.6939, -16.7891) to (-24.1812, -19.3017) ccw
      arc A8 centre (-48.9356, -14.0856) radius 5.2161 from (-48.9356, -19.3017) to (-43.8676, -15.3198) ccw
      arc A9 centre (-50.1239, -14.8594) radius 4.4424 from (-54.3874, -16.1072) to (-50.1239, -19.3017) ccw
      arc A10 centre (-62.8479, -5) radius 5 from (-62.8479, 0) to (-58.0492, -3.5955) cw
      arc A11 centre (-52.1939, 0.1889) radius 3.6826 from (-55.7282, -0.8455) to (-52.1939, -3.4937) ccw
      arc A12 centre (-47.975, 0.1697) radius 3.6634 from (-47.975, -3.4937) to (-44.4156, -0.6971) ccw
      arc A13 centre (-75.055, 2.8937) radius 2.8937 from (-77.9488, 2.8937) to (-75.055, 0) ccw
      arc A14 centre (-74.7475, 12.497) radius 3.2013 from (-77.9488, 12.497) to (-74.7475, 15.6983) cw
      arc A15 centre (-65.0658, 9.6983) radius 6 from (-65.0658, 15.6983) to (-59.3074, 11.3836) cw
      reference intersected line E5 (49.3512, -5.3517) -> (49.3512, -15.4984) from face of Solid3
      reference projected line E6 (-8.3488, 15.6983) -> (-12.6313, 15.6983) from edge [face of Solid3 | face of Solid3]
      reference projected line E7 (-0.0488, -5.3517) -> (-0.0488, -15.4984) from edge [face of Solid3 | face of Solid3]
      radius A1 = 6.376
      radius A2 = 11.0643
      radius A3 = 6.3557
      radius A4 = 3.4217
      radius A5 = 9.1545
      radius A6 = 4.7077
      radius A7 = 2.5127
      radius A8 = 5.2161
      radius A9 = 4.4424
      radius A10 = 5
      radius A11 = 3.6826
      radius A12 = 3.6634
      radius A13 = 2.8937
      radius A14 = 3.2013
      radius A15 = 6
      distance E5 L1 = 127.3
      angle L3 L5 = 30
      distance L4 L15 = 35
      distance L2 H = 0
      angle L16 L13 = 13.6866
      distance L11 E7 = 16.7
      distance L18 L3 = 3
      distance L16 L5 = 3.9924
      vertical: L1 V, L11 V, L13 V
      horizontal: L2 H, L4 H, L6 H, L9 H, L12 H, L15 H, L17 H, L19 H
      coincidence: P1 H, P2 L4, L6 P1, L5 P1, L8 P2, L9 P2, E6 L15, L19 L15
      tangency: A1 L12, A1 L13, A2 L7, A2 L8, A3 L6, A3 L7, A4 L6, A4 L5, A5 L11, A5 L10, A6 L9, A6 L10, A7 L8, A7 L9, A8 L4, A8 L5, A9 L3, A9 L4, A10 L2, A10 L3, A11 L18, A11 L17, A12 L17, A12 L16, A13 L1, A13 L2, A14 L1, A14 L19, A15 L19, A15 L18
      parallelism: L11 L8
    Pad2: profile Sketch20, direction (0, 0, 1), length 14
    Sketch21 on yz-plane, origin (0, 0, 0), H (0, 1, 0), V (0, 0, 1)
      projected line E1 (-5.1983, 2.65) -> (-11.1983, 2.65) from edge [face of Solid2 | face of Solid2]
      projected arc E2 centre (-11.1982, 0.15) radius 2.5 from (-11.1983, 2.65) to (-13.6983, 0.15) ccw from edge [face of Solid2 | face of Solid2]
      projected arc E3 centre (-11.1982, 0.15) radius 2.5 from (-13.6983, 0.15) to (-11.1983, -2.35) ccw from edge [face of Solid2 | face of Solid2]
      projected line E4 (-5.1983, -2.35) -> (-11.1983, -2.35) from edge [face of Solid2 | face of Solid2]
      projected arc E5 centre (-5.1982, 0.15) radius 2.5 from (-4.1662, -2.127) to (-2.6983, 0.15) ccw from edge [face of Solid2 | face of Solid2]
      projected arc E6 centre (-5.1983, 0.15) radius 2.5 from (-5.1983, -2.35) to (-4.1662, -2.127) ccw from edge [face of Solid2 | face of Solid2]
      projected arc E7 centre (-5.1982, 0.15) radius 2.5 from (-2.6983, 0.15) to (-4.1662, 2.427) ccw from edge [face of Solid2 | face of Solid2]
      projected arc E8 centre (-5.1983, 0.15) radius 2.5 from (-4.1662, 2.427) to (-5.1983, 2.65) ccw from edge [face of Solid2 | face of Solid2]
      projected arc E9 centre (8.2017, 0.15) radius 2.5 from (8.2017, 2.65) to (8.2017, -2.35) ccw from edge [face of Solid2 | face of Solid2]
      projected line E10 (8.2017, 2.65) -> (14.2017, 2.65) from edge [face of Solid2 | face of Solid2]
      projected arc E11 centre (14.2017, 0.15) radius 2.5 from (15.7359, 2.1239) to (14.2017, 2.65) ccw from edge [face of Solid2 | face of Solid2]
      projected arc E12 centre (14.2018, 0.15) radius 2.5 from (16.7017, 0.15) to (15.7359, 2.1239) ccw from edge [face of Solid2 | face of Solid2]
      projected arc E13 centre (14.2018, 0.15) radius 2.5 from (15.7359, -1.8239) to (16.7017, 0.15) ccw from edge [face of Solid2 | face of Solid2]
      projected arc E14 centre (14.2017, 0.15) radius 2.5 from (14.2017, -2.35) to (15.7359, -1.8239) ccw from edge [face of Solid2 | face of Solid2]
      projected line E15 (14.2017, -2.35) -> (8.2017, -2.35) from edge [face of Solid2 | face of Solid2]
    Pocket9: profile Sketch21, direction (-1, 0, 0), length 129
    Sketch22 on start face of Pad2, origin (0, 0, -6.85), H (1, 0, 0), V (0, -1, 0)
      projected line E1 (-23.0734, -12.4815) -> (-23.0734, -8.1875) from edge [face of Solid2 | face of Solid2]
      projected arc E2 centre (-21.0389, -8.1878) radius 2.0345 from (-19.0043, -8.1875) to (-23.0734, -8.1875) ccw from edge [face of Solid2 | face of Solid2]
      projected line E3 (-19.0044, -8.1875) -> (-19.0044, -12.4815) from edge [face of Solid2 | face of Solid2]
      projected arc E4 centre (-21.0389, -12.4811) radius 2.0345 from (-23.0734, -12.4815) to (-19.0044, -12.4815) ccw from edge [face of Solid2 | face of Solid2]
      projected line E5 (-31.8873, 9.9683) -> (-31.8873, 6.6556) from edge [face of Solid2 | face of Solid2]
      projected arc E6 centre (-33.637, 9.9684) radius 1.7496 from (-31.8873, 9.9683) to (-33.6371, 11.718) ccw from edge [face of Solid2 | face of Solid2]
      projected line E7 (-35.7044, 11.718) -> (-33.6371, 11.718) from edge [face of Solid2 | face of Solid2]
      projected arc E8 centre (-35.7045, 10.7182) radius 0.9998 from (-35.7044, 11.718) to (-36.6716, 10.9719) ccw from edge [face of Solid2 | face of Solid2]
      projected line E9 (-37.7695, 6.7862) -> (-36.6716, 10.9719) from edge [face of Solid2 | face of Solid2]
      projected arc E10 centre (-36.319, 6.4055) radius 1.4997 from (-37.7695, 6.7862) to (-36.3188, 4.9059) ccw from edge [face of Solid2 | face of Solid2]
      projected line E11 (-33.6371, 4.9059) -> (-36.3188, 4.9059) from edge [face of Solid2 | face of Solid2]
      projected arc E12 centre (-33.637, 6.6555) radius 1.7496 from (-33.6371, 4.9059) to (-31.8873, 6.6556) ccw from edge [face of Solid2 | face of Solid2]
      projected line E13 (-48.4926, -7.4437) -> (-49.8869, -7.4437) from edge [face of Solid2 | face of Solid2]
      projected curve E14 from edge [face of Solid2 | face of Solid2]
      projected line E15 (-51.798, -10.0318) -> (-50.6622, -13.7207) from edge [face of Solid2 | face of Solid2]
      projected curve E16 from edge [face of Solid2 | face of Solid2]
      projected curve E17 from edge [face of Solid2 | face of Solid2]
      projected line E18 (-49.2288, -14.7792) -> (-48.8515, -14.7792) from edge [face of Solid2 | face of Solid2]
      projected line E19 (-47.3891, -13.6117) -> (-46.5426, -9.8864) from edge [face of Solid2 | face of Solid2]
      projected curve E20 from edge [face of Solid2 | face of Solid2]
      projected line E21 (-64.0401, 11.1111) -> (-70.083, 11.1111) from edge [face of Solid2 | face of Solid2]
      projected curve E22 from edge [face of Solid2 | face of Solid2]
      projected line E23 (-61.4946, 7.5571) -> (-62.1226, 9.6789) from edge [face of Solid2 | face of Solid2]
      projected curve E24 from edge [face of Solid2 | face of Solid2]
      projected line E25 (-70.083, 5.0483) -> (-63.3121, 5.0483) from edge [face of Solid2 | face of Solid2]
      projected curve E26 from edge [face of Solid2 | face of Solid2]
      projected line E27 (-72.0827, 9.1114) -> (-72.0827, 7.048) from edge [face of Solid2 | face of Solid2]
      projected curve E28 from edge [face of Solid2 | face of Solid2]
      projected arc E29 centre (-63.414, 6.9893) radius 2.0016 from (-61.4124, 6.9896) to (-61.4946, 7.5571) ccw from edge [face of Solid2 | face of Solid2]
      projected line E30 (-61.4124, 6.948) -> (-61.4124, 6.9896) from edge [face of Solid2 | face of Solid2]
    Pocket10: profile Sketch22, direction (0, 0, 1), length 6
    Sketch23 on face of Pad2 from Sketch20.L1, origin (-77.9488, 0, 0), H (0, -1, 0), V (0, 0, 1)
      projected line E1 (5.1983, 2.65) -> (11.1983, 2.65) from edge [face of Pocket9 from Sketch21.E1 | face of Pad2 from Sketch20.L1]
      projected line E2 (5.1982, 2.65) -> (11.1983, 2.65) from edge [face of Pocket9 from Sketch21.E1 | face of Pad2 from Sketch20.L1]
      point P2 (11.1983, 2.65)
      projected arc E3 centre (11.1982, 0.15) radius 2.5 from (12.497, 2.2862) to (11.1983, 2.65) ccw from edge [face of Pocket9 from Sketch21.E2 | face of Pad2 from Sketch20.L1]
      point P4 (11.1983, 2.65)
      projected arc E4 centre (11.1982, 0.15) radius 2.5 from (13.6983, 0.15) to (12.497, 2.2862) ccw from edge [face of Pad2 from Sketch20.A14 | face of Pocket9 from Sketch21.E2]
      projected arc E5 centre (11.1982, 0.15) radius 2.5 from (12.497, -1.9862) to (13.6983, 0.15) ccw from edge [face of Pocket9 from Sketch21.E3 | face of Pad2 from Sketch20.A14]
      projected arc E6 centre (11.1982, 0.15) radius 2.5 from (11.1983, -2.35) to (12.497, -1.9862) ccw from edge [face of Pocket9 from Sketch21.E3 | face of Pad2 from Sketch20.L1]
      point P9 (11.1983, -2.35)
      projected line E7 (5.1983, -2.35) -> (11.1983, -2.35) from edge [face of Pad2 from Sketch20.L1 | face of Pocket9 from Sketch21.E4]
      projected line E8 (5.1982, -2.35) -> (11.1983, -2.35) from edge [face of Pad2 from Sketch20.L1 | face of Pocket9 from Sketch21.E4]
      point P12 (11.1983, -2.35)
      arc A1 centre (5.1982, 0.15) radius 2.5 from (5.1982, -2.35) to (5.1982, 2.65) ccw
      reference projected arc E9 centre (5.1982, 0.15) radius 2.5 from (4.1662, 2.427) to (2.8937, 1.1191) ccw from edge [face of Pocket9 from Sketch21.E7 | face of Pad2 from Sketch20.L1]
      reference projected arc E10 centre (5.1982, 0.15) radius 2.5 from (4.1662, 2.427) to (2.8937, 1.1191) ccw from edge [face of Pocket9 from Sketch21.E7 | face of Pad2 from Sketch20.L1]
      concentricity: A1 E9
      coincidence: A1 E10, P2 P4, P9 P12
    Pad3: profile Sketch23, direction (1, 0, 0), up to face of Pocket10 from Sketch22.E27
    Sketch24 on start face of Pad2, origin (0, 0, -6.85), H (1, 0, 0), V (0, -1, 0)
      projected arc E1 centre (-74.7475, 12.497) radius 3.2013 from (-74.7475, 15.6983) to (-77.9488, 12.497) ccw from edge [face of Pad2 from Sketch20.A14 | start face of Pad2]
    Pocket11: profile Sketch24, direction (0, 0, 1), length 43
  Add1: tool Body5
  Split14: SplitPlane face of Solid3
  Split15: SplitPlane face of Solid3
  Split16: SplitPlane face of Solid3
  Split17: SplitPlane face of Solid3
  Split18: SplitPlane face of Solid3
